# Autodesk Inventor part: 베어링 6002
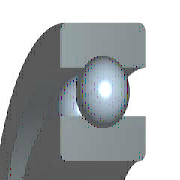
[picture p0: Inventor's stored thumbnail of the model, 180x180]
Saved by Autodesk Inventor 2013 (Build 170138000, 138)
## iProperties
Created: 2012-02
Part Number: 베어링 6002
Material: 강철, 연강
Description: 깊은 그루브 볼 베어링
Document SubType Name: Modeling
Standard: KS B 2023
Designer: mduedu
Standards Organization: KS
Language: ko-KR
Size Designation: 6002 - 15 x 32 x 9
Categories: <MemberInstance><Categories><Category DisplayName="샤프트 부품" InternalName="7f7aeb1f-a693-4053-b835-cee3144e0d98" Mnemonic="SHFT"><Category DisplayName="베어링" Inter
Density: 7.86 g/cm^3
Mass: 29.8124 g
Surface Area: 39.9079 cm^2
Volume: 3.79293 cm^3
IsCustomPart: 1
Author: mduedu
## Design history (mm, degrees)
sketch "스케치" dims "d0" = 4.42 (= -0.26 x WD + 0.26 x BD)
  geometry: L1 (2.29, 11.75)-(6.71, 11.75); L2 (4.5, 11.75)-(4.5, 9.54); L3 (4.5, 11.75)-(4.5, 13.96); L4 (2.858, 10.271)-(0, 10.271); L5 (0, 7.5)-(9, 7.5); L6 (2.858, 13.229)-(0, 13.229); L7 (0, 16)-(9, 16); L8 (9, 7.5)-(9, 10.271); L9 (6.142, 10.271)-(9, 10.271); L10 (6.142, 13.229)-(9, 13.229); L11 (9, 16)-(9, 13.229); L12 (-1.4, 0)-(8.4, 0) reference; L13 (0, -0.3)-(0, 5.3) reference
  constraints: 22 end point, 4 point on line, 2 collinear, 2 perpendicular, 2 symmetric about line, 1 midpoint, 1 parallel, 14 other
  dimensions: "d9" = 15 diameter of L5 L12 (= WD); "d11" = 32 diameter of L7 L12 (= BD); "d12" = 9 distance between parallel lines of L8 L13 (= KB); "d13" = 20.542 diameter of L9 L12 (= 0.326 x BD + 0.674 x WD)
revolve "본체" stored, may be unused: angle "d6" = 90 deg
revolve "볼" stored, may be unused: angle "d7" = 90 deg
pattern_circular "IDS_ARRAYBALL[SIMPL:T]" dims angle "d3" = 360 deg
body "Solid1"
fillet "모깎기1" dims "d1" = 0.3 (= KRS)
other parameters: "WD" = 15 [user parameter; used in 5 equation terms], "BD" = 32 [user parameter; used in 5 equation terms], "KB" = 9 [user parameter; used in 1 equation term], "KRS" = 0.3 [user parameter; used in 1 equation term], "d4" = 0, "d5" = 0, "d8" = 0, "d14" = 0, "d15" = 0, "BBA" = 0 [user parameter], "BC0" = 2850000 [user parameter], "BC" = 5590000 [user parameter], "BR" = 16 (= 0.5 x BD) [user parameter], "WR" = 7.5 (= 0.5 x WD) [user parameter]
